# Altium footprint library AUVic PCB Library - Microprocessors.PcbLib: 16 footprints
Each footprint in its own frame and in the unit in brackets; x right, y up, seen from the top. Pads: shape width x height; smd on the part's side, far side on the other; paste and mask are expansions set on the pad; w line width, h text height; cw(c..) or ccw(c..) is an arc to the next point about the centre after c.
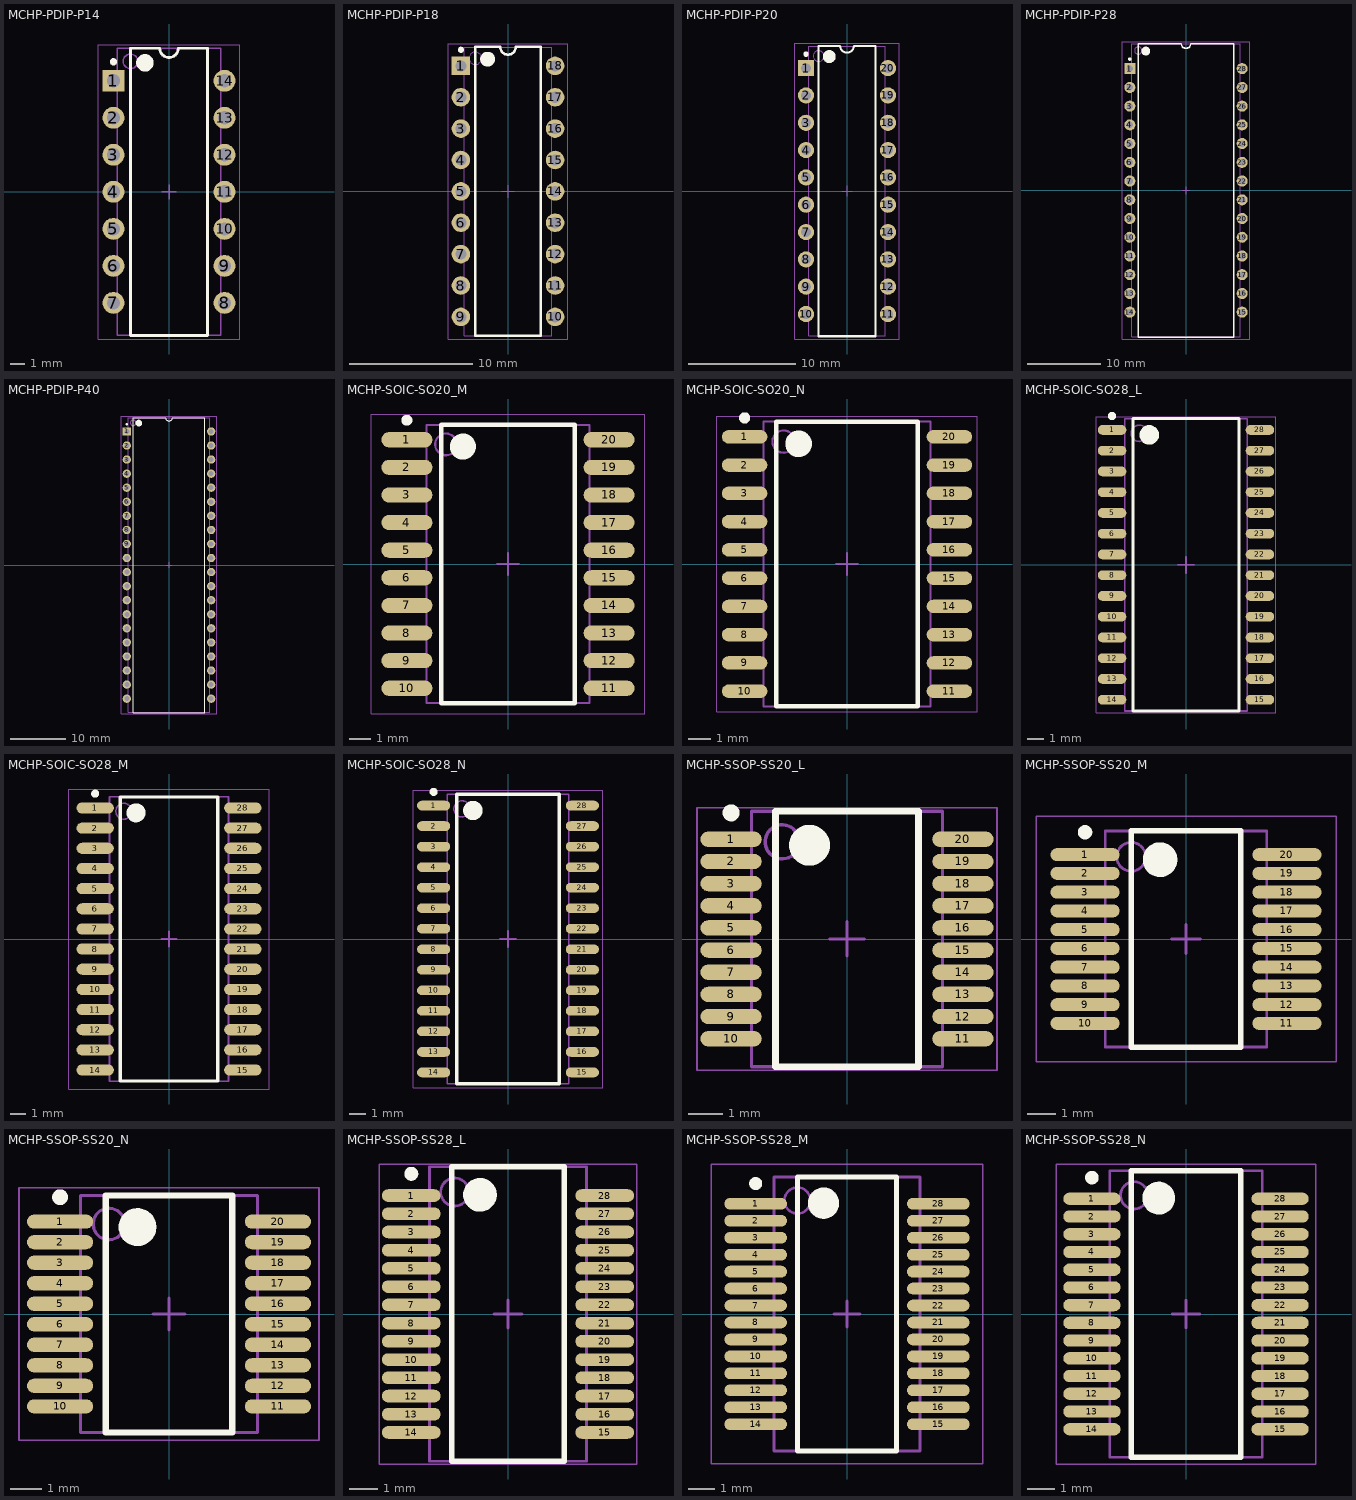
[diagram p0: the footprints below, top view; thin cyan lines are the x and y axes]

## MCHP-PDIP-P14 [mm] "DIP, 14-Leads, Body 19.177x6.604mm, Pitch 2.54mm"
height 5.34
pads (14):
  rect 1.5x1.5 hole 0.9: 1(-3.81,7.62)
  round 1.5 hole 0.9: 2(-3.81,5.08) 3(-3.81,2.54) 4(-3.81,0) 5(-3.81,-2.54) 6(-3.81,-5.08) 7(-3.81,-7.62) 8(3.81,-7.62) 9(3.81,-5.08) 10(3.81,-2.54) 11(3.81,0) 12(3.81,2.54) 13(3.81,5.08) 14(3.81,7.62)
Top Overlay:
  circle w0.25: c-3.81,8.92 r0.125
  circle w0.6: c-1.65,8.85 r0.3
  lines w0.2: -2.65,-9.85 -2.65,9.85 -0.635,9.85 ccw(c0,9.85) 0.635,9.85 2.65,9.85 2.65,-9.85 -2.65,-9.85
Mechanical 13:
  circle w0.1: c-2.65,8.95 r0.5
  lines w0.1: -3.55,-9.85 -3.55,9.85 3.55,9.85 3.55,-9.85 -3.55,-9.85
Mechanical 15:
  lines w0.05: -4.85,-10.1 -4.85,10.1 4.85,10.1 4.85,-10.1 -4.85,-10.1
  lines w0.1: -0.5,0 0.5,0 ; 0,-0.5 0,0.5
3D body: height 2.73, standoff 0, extent -3.945,7.12 -3.675,8.12
3D body: height 3, standoff 2.72, extent -3.945,7.12 -3.55,8.12
3D body: height 0, standoff -1.6, extent -3.945,7.26 -3.675,7.98
3D body: height 2.73, standoff 0, extent -3.945,4.58 -3.675,5.58
3D body: height 3, standoff 2.72, extent -3.945,4.58 -3.55,5.58
3D body: height 0, standoff -1.6, extent -3.945,4.72 -3.675,5.44
3D body: height 2.73, standoff 0, extent -3.945,2.04 -3.675,3.04
3D body: height 3, standoff 2.72, extent -3.945,2.04 -3.55,3.04
3D body: height 0, standoff -1.6, extent -3.945,2.18 -3.675,2.9
3D body: height 2.73, standoff 0, extent -3.945,-0.5 -3.675,0.5
3D body: height 3, standoff 2.72, extent -3.945,-0.5 -3.55,0.5
3D body: height 0, standoff -1.6, extent -3.945,-0.36 -3.675,0.36
3D body: height 2.73, standoff 0, extent -3.945,-3.04 -3.675,-2.04
3D body: height 3, standoff 2.72, extent -3.945,-3.04 -3.55,-2.04
3D body: height 0, standoff -1.6, extent -3.945,-2.9 -3.675,-2.18
3D body: height 2.73, standoff 0, extent -3.945,-5.58 -3.675,-4.58
3D body: height 3, standoff 2.72, extent -3.945,-5.58 -3.55,-4.58
3D body: height 0, standoff -1.6, extent -3.945,-5.44 -3.675,-4.72
3D body: height 2.73, standoff 0, extent -3.945,-8.12 -3.675,-7.12
3D body: height 3, standoff 2.72, extent -3.945,-8.12 -3.55,-7.12
3D body: height 0, standoff -1.6, extent -3.945,-7.98 -3.675,-7.26
3D body: height 2.73, standoff 0, extent 3.675,-8.12 3.945,-7.12
3D body: height 3, standoff 2.72, extent 3.55,-8.12 3.945,-7.12
3D body: height 0, standoff -1.6, extent 3.675,-7.98 3.945,-7.26
3D body: height 2.73, standoff 0, extent 3.675,-5.58 3.945,-4.58
3D body: height 3, standoff 2.72, extent 3.55,-5.58 3.945,-4.58
3D body: height 0, standoff -1.6, extent 3.675,-5.44 3.945,-4.72
3D body: height 2.73, standoff 0, extent 3.675,-3.04 3.945,-2.04
3D body: height 3, standoff 2.72, extent 3.55,-3.04 3.945,-2.04
3D body: height 0, standoff -1.6, extent 3.675,-2.9 3.945,-2.18
3D body: height 2.73, standoff 0, extent 3.675,-0.5 3.945,0.5
3D body: height 3, standoff 2.72, extent 3.55,-0.5 3.945,0.5
3D body: height 0, standoff -1.6, extent 3.675,-0.36 3.945,0.36
3D body: height 2.73, standoff 0, extent 3.675,2.04 3.945,3.04
3D body: height 3, standoff 2.72, extent 3.55,2.04 3.945,3.04
3D body: height 0, standoff -1.6, extent 3.675,2.18 3.945,2.9
3D body: height 2.73, standoff 0, extent 3.675,4.58 3.945,5.58
3D body: height 3, standoff 2.72, extent 3.55,4.58 3.945,5.58
3D body: height 0, standoff -1.6, extent 3.675,4.72 3.945,5.44
3D body: height 2.73, standoff 0, extent 3.675,7.12 3.945,8.12
3D body: height 3, standoff 2.72, extent 3.55,7.12 3.945,8.12
3D body: height 0, standoff -1.6, extent 3.675,7.26 3.945,7.98
3D body: height 5.34, standoff 0.38, extent -3.55,-9.85 3.55,9.85

## MCHP-PDIP-P18 [mm] "DIP, 18-Leads, Body 22.83x6.604mm, Pitch 2.54mm"
height 5.33
pads (18):
  rect 1.5x1.5 hole 0.9: 1(-3.81,10.16)
  round 1.5 hole 0.9: 2(-3.81,7.62) 3(-3.81,5.08) 4(-3.81,2.54) 5(-3.81,0) 6(-3.81,-2.54) 7(-3.81,-5.08) 8(-3.81,-7.62) 9(-3.81,-10.16) 10(3.81,-10.16) 11(3.81,-7.62) 12(3.81,-5.08) 13(3.81,-2.54) 14(3.81,0) 15(3.81,2.54) 16(3.81,5.08) 17(3.81,7.62) 18(3.81,10.16)
Top Overlay:
  circle w0.25: c-3.81,11.46 r0.125
  circle w0.6: c-1.65,10.7 r0.3
  lines w0.2: -2.65,-11.7 -2.65,11.7 -0.635,11.7 ccw(c0,11.7) 0.635,11.7 2.65,11.7 2.65,-11.7 -2.65,-11.7
Mechanical 13:
  circle w0.1: c-2.65,10.775 r0.5
  lines w0.1: -3.55,-11.675 -3.55,11.675 3.55,11.675 3.55,-11.675 -3.55,-11.675
Mechanical 15:
  lines w0.05: -4.85,-11.95 -4.85,11.95 4.85,11.95 4.85,-11.95 -4.85,-11.95
  lines w0.1: -0.5,0 0.5,0 ; 0,-0.5 0,0.5
3D body: height 2.72, standoff 0, extent -3.945,9.66 -3.675,10.66
3D body: height 2.99, standoff 2.72, extent -3.945,9.66 -3.55,10.66
3D body: height 0, standoff -1.6, extent -3.945,9.8 -3.675,10.52
3D body: height 2.72, standoff 0, extent -3.945,7.12 -3.675,8.12
3D body: height 2.99, standoff 2.72, extent -3.945,7.12 -3.55,8.12
3D body: height 0, standoff -1.6, extent -3.945,7.26 -3.675,7.98
3D body: height 2.72, standoff 0, extent -3.945,4.58 -3.675,5.58
3D body: height 2.99, standoff 2.72, extent -3.945,4.58 -3.55,5.58
3D body: height 0, standoff -1.6, extent -3.945,4.72 -3.675,5.44
3D body: height 2.72, standoff 0, extent -3.945,2.04 -3.675,3.04
3D body: height 2.99, standoff 2.72, extent -3.945,2.04 -3.55,3.04
3D body: height 0, standoff -1.6, extent -3.945,2.18 -3.675,2.9
3D body: height 2.72, standoff 0, extent -3.945,-0.5 -3.675,0.5
3D body: height 2.99, standoff 2.72, extent -3.945,-0.5 -3.55,0.5
3D body: height 0, standoff -1.6, extent -3.945,-0.36 -3.675,0.36
3D body: height 2.72, standoff 0, extent -3.945,-3.04 -3.675,-2.04
3D body: height 2.99, standoff 2.72, extent -3.945,-3.04 -3.55,-2.04
3D body: height 0, standoff -1.6, extent -3.945,-2.9 -3.675,-2.18
3D body: height 2.72, standoff 0, extent -3.945,-5.58 -3.675,-4.58
3D body: height 2.99, standoff 2.72, extent -3.945,-5.58 -3.55,-4.58
3D body: height 0, standoff -1.6, extent -3.945,-5.44 -3.675,-4.72
3D body: height 2.72, standoff 0, extent -3.945,-8.12 -3.675,-7.12
3D body: height 2.99, standoff 2.72, extent -3.945,-8.12 -3.55,-7.12
3D body: height 0, standoff -1.6, extent -3.945,-7.98 -3.675,-7.26
3D body: height 2.72, standoff 0, extent -3.945,-10.66 -3.675,-9.66
3D body: height 2.99, standoff 2.72, extent -3.945,-10.66 -3.55,-9.66
3D body: height 0, standoff -1.6, extent -3.945,-10.52 -3.675,-9.8
3D body: height 2.72, standoff 0, extent 3.675,-10.66 3.945,-9.66
3D body: height 2.99, standoff 2.72, extent 3.55,-10.66 3.945,-9.66
3D body: height 0, standoff -1.6, extent 3.675,-10.52 3.945,-9.8
3D body: height 2.72, standoff 0, extent 3.675,-8.12 3.945,-7.12
3D body: height 2.99, standoff 2.72, extent 3.55,-8.12 3.945,-7.12
3D body: height 0, standoff -1.6, extent 3.675,-7.98 3.945,-7.26
3D body: height 2.72, standoff 0, extent 3.675,-5.58 3.945,-4.58
3D body: height 2.99, standoff 2.72, extent 3.55,-5.58 3.945,-4.58
3D body: height 0, standoff -1.6, extent 3.675,-5.44 3.945,-4.72
3D body: height 2.72, standoff 0, extent 3.675,-3.04 3.945,-2.04
3D body: height 2.99, standoff 2.72, extent 3.55,-3.04 3.945,-2.04
3D body: height 0, standoff -1.6, extent 3.675,-2.9 3.945,-2.18
3D body: height 2.72, standoff 0, extent 3.675,-0.5 3.945,0.5
3D body: height 2.99, standoff 2.72, extent 3.55,-0.5 3.945,0.5
3D body: height 0, standoff -1.6, extent 3.675,-0.36 3.945,0.36
3D body: height 2.72, standoff 0, extent 3.675,2.04 3.945,3.04
3D body: height 2.99, standoff 2.72, extent 3.55,2.04 3.945,3.04
3D body: height 0, standoff -1.6, extent 3.675,2.18 3.945,2.9
3D body: height 2.72, standoff 0, extent 3.675,4.58 3.945,5.58
3D body: height 2.99, standoff 2.72, extent 3.55,4.58 3.945,5.58
3D body: height 0, standoff -1.6, extent 3.675,4.72 3.945,5.44
3D body: height 2.72, standoff 0, extent 3.675,7.12 3.945,8.12
3D body: height 2.99, standoff 2.72, extent 3.55,7.12 3.945,8.12
3D body: height 0, standoff -1.6, extent 3.675,7.26 3.945,7.98
3D body: height 2.72, standoff 0, extent 3.675,9.66 3.945,10.66
3D body: height 2.99, standoff 2.72, extent 3.55,9.66 3.945,10.66
3D body: height 0, standoff -1.6, extent 3.675,9.8 3.945,10.52
3D body: height 5.33, standoff 0.38, extent -3.55,-11.675 3.55,11.675

## MCHP-PDIP-P20 [mm] "DIP, 20-Leads, Body 25.91x6.6mm, Pitch 2.54mm"
height 5.34
pads (20):
  rect 1.5x1.5 hole 0.9: 1(-3.81,11.43)
  round 1.5 hole 0.9: 2(-3.81,8.89) 3(-3.81,6.35) 4(-3.81,3.81) 5(-3.81,1.27) 6(-3.81,-1.27) 7(-3.81,-3.81) 8(-3.81,-6.35) 9(-3.81,-8.89) 10(-3.81,-11.43) 11(3.81,-11.43) 12(3.81,-8.89) 13(3.81,-6.35) 14(3.81,-3.81) 15(3.81,-1.27) 16(3.81,1.27) 17(3.81,3.81) 18(3.81,6.35) 19(3.81,8.89) 20(3.81,11.43)
Top Overlay:
  circle w0.25: c-3.81,12.73 r0.125
  circle w0.6: c-1.65,12.5 r0.3
  lines w0.2: -2.65,-13.5 -2.65,13.5 -0.635,13.5 ccw(c0,13.5) 0.635,13.5 2.65,13.5 2.65,-13.5 -2.65,-13.5
Mechanical 13:
  circle w0.1: c-2.65,12.55 r0.5
  lines w0.1: -3.55,-13.45 -3.55,13.45 3.55,13.45 3.55,-13.45 -3.55,-13.45
Mechanical 15:
  lines w0.05: -4.85,-13.75 -4.85,13.75 4.85,13.75 4.85,-13.75 -4.85,-13.75
  lines w0.1: -0.5,0 0.5,0 ; 0,-0.5 0,0.5
3D body: height 2.72, standoff 0, extent -3.945,10.93 -3.675,11.93
3D body: height 2.99, standoff 2.72, extent -3.945,10.93 -3.55,11.93
3D body: height 0, standoff -1.6, extent -3.945,11.07 -3.675,11.79
3D body: height 2.72, standoff 0, extent -3.945,8.39 -3.675,9.39
3D body: height 2.99, standoff 2.72, extent -3.945,8.39 -3.55,9.39
3D body: height 0, standoff -1.6, extent -3.945,8.53 -3.675,9.25
3D body: height 2.72, standoff 0, extent -3.945,5.85 -3.675,6.85
3D body: height 2.99, standoff 2.72, extent -3.945,5.85 -3.55,6.85
3D body: height 0, standoff -1.6, extent -3.945,5.99 -3.675,6.71
3D body: height 2.72, standoff 0, extent -3.945,3.31 -3.675,4.31
3D body: height 2.99, standoff 2.72, extent -3.945,3.31 -3.55,4.31
3D body: height 0, standoff -1.6, extent -3.945,3.45 -3.675,4.17
3D body: height 2.72, standoff 0, extent -3.945,0.77 -3.675,1.77
3D body: height 2.99, standoff 2.72, extent -3.945,0.77 -3.55,1.77
3D body: height 0, standoff -1.6, extent -3.945,0.91 -3.675,1.63
3D body: height 2.72, standoff 0, extent -3.945,-1.77 -3.675,-0.77
3D body: height 2.99, standoff 2.72, extent -3.945,-1.77 -3.55,-0.77
3D body: height 0, standoff -1.6, extent -3.945,-1.63 -3.675,-0.91
3D body: height 2.72, standoff 0, extent -3.945,-4.31 -3.675,-3.31
3D body: height 2.99, standoff 2.72, extent -3.945,-4.31 -3.55,-3.31
3D body: height 0, standoff -1.6, extent -3.945,-4.17 -3.675,-3.45
3D body: height 2.72, standoff 0, extent -3.945,-6.85 -3.675,-5.85
3D body: height 2.99, standoff 2.72, extent -3.945,-6.85 -3.55,-5.85
3D body: height 0, standoff -1.6, extent -3.945,-6.71 -3.675,-5.99
3D body: height 2.72, standoff 0, extent -3.945,-9.39 -3.675,-8.39
3D body: height 2.99, standoff 2.72, extent -3.945,-9.39 -3.55,-8.39
3D body: height 0, standoff -1.6, extent -3.945,-9.25 -3.675,-8.53
3D body: height 2.72, standoff 0, extent -3.945,-11.93 -3.675,-10.93
3D body: height 2.99, standoff 2.72, extent -3.945,-11.93 -3.55,-10.93
3D body: height 0, standoff -1.6, extent -3.945,-11.79 -3.675,-11.07
3D body: height 2.72, standoff 0, extent 3.675,-11.93 3.945,-10.93
3D body: height 2.99, standoff 2.72, extent 3.55,-11.93 3.945,-10.93
3D body: height 0, standoff -1.6, extent 3.675,-11.79 3.945,-11.07
3D body: height 2.72, standoff 0, extent 3.675,-9.39 3.945,-8.39
3D body: height 2.99, standoff 2.72, extent 3.55,-9.39 3.945,-8.39
3D body: height 0, standoff -1.6, extent 3.675,-9.25 3.945,-8.53
3D body: height 2.72, standoff 0, extent 3.675,-6.85 3.945,-5.85
3D body: height 2.99, standoff 2.72, extent 3.55,-6.85 3.945,-5.85
3D body: height 0, standoff -1.6, extent 3.675,-6.71 3.945,-5.99
3D body: height 2.72, standoff 0, extent 3.675,-4.31 3.945,-3.31
3D body: height 2.99, standoff 2.72, extent 3.55,-4.31 3.945,-3.31
3D body: height 0, standoff -1.6, extent 3.675,-4.17 3.945,-3.45
3D body: height 2.72, standoff 0, extent 3.675,-1.77 3.945,-0.77
3D body: height 2.99, standoff 2.72, extent 3.55,-1.77 3.945,-0.77
3D body: height 0, standoff -1.6, extent 3.675,-1.63 3.945,-0.91
3D body: height 2.72, standoff 0, extent 3.675,0.77 3.945,1.77
3D body: height 2.99, standoff 2.72, extent 3.55,0.77 3.945,1.77
3D body: height 0, standoff -1.6, extent 3.675,0.91 3.945,1.63
3D body: height 2.72, standoff 0, extent 3.675,3.31 3.945,4.31
3D body: height 2.99, standoff 2.72, extent 3.55,3.31 3.945,4.31
3D body: height 0, standoff -1.6, extent 3.675,3.45 3.945,4.17
3D body: height 2.72, standoff 0, extent 3.675,5.85 3.945,6.85
3D body: height 2.99, standoff 2.72, extent 3.55,5.85 3.945,6.85
3D body: height 0, standoff -1.6, extent 3.675,5.99 3.945,6.71
3D body: height 2.72, standoff 0, extent 3.675,8.39 3.945,9.39
3D body: height 2.99, standoff 2.72, extent 3.55,8.39 3.945,9.39
3D body: height 0, standoff -1.6, extent 3.675,8.53 3.945,9.25
3D body: height 2.72, standoff 0, extent 3.675,10.93 3.945,11.93
3D body: height 2.99, standoff 2.72, extent 3.55,10.93 3.945,11.93
3D body: height 0, standoff -1.6, extent 3.675,11.07 3.945,11.79
3D body: height 5.34, standoff 0.38, extent -3.55,-13.45 3.55,13.45

## MCHP-PDIP-P28 [mm] "DIP, 28-Leads, Body 37.4x13.53mm, Pitch 2.54mm"
height 6.35
pads (28):
  rect 1.5x1.5 hole 0.9: 1(-7.62,16.51)
  round 1.5 hole 0.9: 2(-7.62,13.97) 3(-7.62,11.43) 4(-7.62,8.89) 5(-7.62,6.35) 6(-7.62,3.81) 7(-7.62,1.27) 8(-7.62,-1.27) 9(-7.62,-3.81) 10(-7.62,-6.35) 11(-7.62,-8.89) 12(-7.62,-11.43) 13(-7.62,-13.97) 14(-7.62,-16.51) 15(7.62,-16.51) 16(7.62,-13.97) 17(7.62,-11.43) 18(7.62,-8.89) 19(7.62,-6.35) 20(7.62,-3.81) 21(7.62,-1.27) 22(7.62,1.27) 23(7.62,3.81) 24(7.62,6.35) 25(7.62,8.89) 26(7.62,11.43) 27(7.62,13.97) 28(7.62,16.51)
Top Overlay:
  circle w0.6: c-5.45,18.9 r0.3
  circle w0.25: c-7.62,17.81 r0.125
  lines w0.2: -6.45,-19.9 6.45,-19.9 6.45,19.9 0.635,19.9 cw(c0,19.9) -0.635,19.9 -6.45,19.9 -6.45,-19.9
Mechanical 13:
  circle w0.1: c-6.475,18.975 r0.5
  lines w0.1: -7.375,-19.875 7.375,-19.875 7.375,19.875 -7.375,19.875 -7.375,-19.875
Mechanical 15:
  lines w0.05: -8.65,-20.15 8.65,-20.15 8.65,20.15 -8.65,20.15 -8.65,-20.15
  lines w0.1: -0.5,0 0.5,0 ; 0,-0.5 0,0.5
3D body: height 6.35, standoff 0.38, extent -7.375,-19.875 7.375,19.875
3D body: height 0, standoff -1.6, extent 7.485,16.15 7.755,16.87
3D body: height 3.51, standoff 3.23, extent 7.375,16.01 7.755,17.01
3D body: height 3.24, standoff 0, extent 7.485,16.01 7.755,17.01
3D body: height 0, standoff -1.6, extent 7.485,13.61 7.755,14.33
3D body: height 3.51, standoff 3.23, extent 7.375,13.47 7.755,14.47
3D body: height 3.24, standoff 0, extent 7.485,13.47 7.755,14.47
3D body: height 0, standoff -1.6, extent 7.485,11.07 7.755,11.79
3D body: height 3.51, standoff 3.23, extent 7.375,10.93 7.755,11.93
3D body: height 3.24, standoff 0, extent 7.485,10.93 7.755,11.93
3D body: height 0, standoff -1.6, extent 7.485,8.53 7.755,9.25
3D body: height 3.51, standoff 3.23, extent 7.375,8.39 7.755,9.39
3D body: height 3.24, standoff 0, extent 7.485,8.39 7.755,9.39
3D body: height 0, standoff -1.6, extent 7.485,5.99 7.755,6.71
3D body: height 3.51, standoff 3.23, extent 7.375,5.85 7.755,6.85
3D body: height 3.24, standoff 0, extent 7.485,5.85 7.755,6.85
3D body: height 0, standoff -1.6, extent 7.485,3.45 7.755,4.17
3D body: height 3.51, standoff 3.23, extent 7.375,3.31 7.755,4.31
3D body: height 3.24, standoff 0, extent 7.485,3.31 7.755,4.31
3D body: height 0, standoff -1.6, extent 7.485,0.91 7.755,1.63
3D body: height 3.51, standoff 3.23, extent 7.375,0.77 7.755,1.77
3D body: height 3.24, standoff 0, extent 7.485,0.77 7.755,1.77
3D body: height 0, standoff -1.6, extent 7.485,-1.63 7.755,-0.91
3D body: height 3.51, standoff 3.23, extent 7.375,-1.77 7.755,-0.77
3D body: height 3.24, standoff 0, extent 7.485,-1.77 7.755,-0.77
3D body: height 0, standoff -1.6, extent 7.485,-4.17 7.755,-3.45
3D body: height 3.51, standoff 3.23, extent 7.375,-4.31 7.755,-3.31
3D body: height 3.24, standoff 0, extent 7.485,-4.31 7.755,-3.31
3D body: height 0, standoff -1.6, extent 7.485,-6.71 7.755,-5.99
3D body: height 3.51, standoff 3.23, extent 7.375,-6.85 7.755,-5.85
3D body: height 3.24, standoff 0, extent 7.485,-6.85 7.755,-5.85
3D body: height 0, standoff -1.6, extent 7.485,-9.25 7.755,-8.53
3D body: height 3.51, standoff 3.23, extent 7.375,-9.39 7.755,-8.39
3D body: height 3.24, standoff 0, extent 7.485,-9.39 7.755,-8.39
3D body: height 0, standoff -1.6, extent 7.485,-11.79 7.755,-11.07
3D body: height 3.51, standoff 3.23, extent 7.375,-11.93 7.755,-10.93
3D body: height 3.24, standoff 0, extent 7.485,-11.93 7.755,-10.93
3D body: height 0, standoff -1.6, extent 7.485,-14.33 7.755,-13.61
3D body: height 3.51, standoff 3.23, extent 7.375,-14.47 7.755,-13.47
3D body: height 3.24, standoff 0, extent 7.485,-14.47 7.755,-13.47
3D body: height 0, standoff -1.6, extent 7.485,-16.87 7.755,-16.15
3D body: height 3.51, standoff 3.23, extent 7.375,-17.01 7.755,-16.01
3D body: height 3.24, standoff 0, extent 7.485,-17.01 7.755,-16.01
3D body: height 0, standoff -1.6, extent -7.755,-16.87 -7.485,-16.15
3D body: height 3.51, standoff 3.23, extent -7.755,-17.01 -7.375,-16.01
3D body: height 3.24, standoff 0, extent -7.755,-17.01 -7.485,-16.01
3D body: height 0, standoff -1.6, extent -7.755,-14.33 -7.485,-13.61
3D body: height 3.51, standoff 3.23, extent -7.755,-14.47 -7.375,-13.47
3D body: height 3.24, standoff 0, extent -7.755,-14.47 -7.485,-13.47
3D body: height 0, standoff -1.6, extent -7.755,-11.79 -7.485,-11.07
3D body: height 3.51, standoff 3.23, extent -7.755,-11.93 -7.375,-10.93
3D body: height 3.24, standoff 0, extent -7.755,-11.93 -7.485,-10.93
3D body: height 0, standoff -1.6, extent -7.755,-9.25 -7.485,-8.53
3D body: height 3.51, standoff 3.23, extent -7.755,-9.39 -7.375,-8.39
3D body: height 3.24, standoff 0, extent -7.755,-9.39 -7.485,-8.39
3D body: height 0, standoff -1.6, extent -7.755,-6.71 -7.485,-5.99
3D body: height 3.51, standoff 3.23, extent -7.755,-6.85 -7.375,-5.85
3D body: height 3.24, standoff 0, extent -7.755,-6.85 -7.485,-5.85
3D body: height 0, standoff -1.6, extent -7.755,-4.17 -7.485,-3.45
3D body: height 3.51, standoff 3.23, extent -7.755,-4.31 -7.375,-3.31
3D body: height 3.24, standoff 0, extent -7.755,-4.31 -7.485,-3.31
3D body: height 0, standoff -1.6, extent -7.755,-1.63 -7.485,-0.91
3D body: height 3.51, standoff 3.23, extent -7.755,-1.77 -7.375,-0.77
3D body: height 3.24, standoff 0, extent -7.755,-1.77 -7.485,-0.77
3D body: height 0, standoff -1.6, extent -7.755,0.91 -7.485,1.63
3D body: height 3.51, standoff 3.23, extent -7.755,0.77 -7.375,1.77
3D body: height 3.24, standoff 0, extent -7.755,0.77 -7.485,1.77
3D body: height 0, standoff -1.6, extent -7.755,3.45 -7.485,4.17
3D body: height 3.51, standoff 3.23, extent -7.755,3.31 -7.375,4.31
3D body: height 3.24, standoff 0, extent -7.755,3.31 -7.485,4.31
3D body: height 0, standoff -1.6, extent -7.755,5.99 -7.485,6.71
3D body: height 3.51, standoff 3.23, extent -7.755,5.85 -7.375,6.85
3D body: height 3.24, standoff 0, extent -7.755,5.85 -7.485,6.85
3D body: height 0, standoff -1.6, extent -7.755,8.53 -7.485,9.25
3D body: height 3.51, standoff 3.23, extent -7.755,8.39 -7.375,9.39
3D body: height 3.24, standoff 0, extent -7.755,8.39 -7.485,9.39
3D body: height 0, standoff -1.6, extent -7.755,11.07 -7.485,11.79
3D body: height 3.51, standoff 3.23, extent -7.755,10.93 -7.375,11.93
3D body: height 3.24, standoff 0, extent -7.755,10.93 -7.485,11.93
3D body: height 0, standoff -1.6, extent -7.755,13.61 -7.485,14.33
3D body: height 3.51, standoff 3.23, extent -7.755,13.47 -7.375,14.47
3D body: height 3.24, standoff 0, extent -7.755,13.47 -7.485,14.47
3D body: height 0, standoff -1.6, extent -7.755,16.15 -7.485,16.87
3D body: height 3.51, standoff 3.23, extent -7.755,16.01 -7.375,17.01
3D body: height 3.24, standoff 0, extent -7.755,16.01 -7.485,17.01

## MCHP-PDIP-P40 [mm] "PDIP, 40-Leads, Body 51.75x13.53mm, Pitch 2.54mm"
height 6.35
pads (40):
  rect 1.5x1.5 hole 0.9: 1(-7.62,24.13)
  round 1.5 hole 0.9: 2(-7.62,21.59) 3(-7.62,19.05) 4(-7.62,16.51) 5(-7.62,13.97) 6(-7.62,11.43) 7(-7.62,8.89) 8(-7.62,6.35) 9(-7.62,3.81) 10(-7.62,1.27) 11(-7.62,-1.27) 12(-7.62,-3.81) 13(-7.62,-6.35) 14(-7.62,-8.89) 15(-7.62,-11.43) 16(-7.62,-13.97) 17(-7.62,-16.51) 18(-7.62,-19.05) 19(-7.62,-21.59) 20(-7.62,-24.13) 21(7.62,-24.13) 22(7.62,-21.59) 23(7.62,-19.05) 24(7.62,-16.51) 25(7.62,-13.97) 26(7.62,-11.43) 27(7.62,-8.89) 28(7.62,-6.35) 29(7.62,-3.81) 30(7.62,-1.27) 31(7.62,1.27) 32(7.62,3.81) 33(7.62,6.35) 34(7.62,8.89) 35(7.62,11.43) 36(7.62,13.97) 37(7.62,16.51) 38(7.62,19.05) 39(7.62,21.59) 40(7.62,24.13)
Top Overlay:
  circle w0.6: c-5.45,25.65 r0.3
  circle w0.25: c-7.62,25.43 r0.125
  lines w0.2: -6.45,-26.65 6.45,-26.65 6.45,26.65 0.635,26.65 cw(c0,26.65) -0.635,26.65 -6.45,26.65 -6.45,-26.65
Mechanical 13:
  circle w0.1: c-6.475,25.7 r0.5
  lines w0.1: -7.375,-26.6 7.375,-26.6 7.375,26.6 -7.375,26.6 -7.375,-26.6
Mechanical 15:
  lines w0.05: -8.65,-26.9 8.65,-26.9 8.65,26.9 -8.65,26.9 -8.65,-26.9
  lines w0.1: -0.5,0 0.5,0 ; 0,-0.5 0,0.5
3D body: height 6.35, standoff 0.38, extent -7.375,-26.6 7.375,26.6
3D body: height 0, standoff -1.6, extent 7.485,23.77 7.755,24.49
3D body: height 3.51, standoff 3.23, extent 7.375,23.63 7.755,24.63
3D body: height 3.24, standoff 0, extent 7.485,23.63 7.755,24.63
3D body: height 0, standoff -1.6, extent 7.485,21.23 7.755,21.95
3D body: height 3.51, standoff 3.23, extent 7.375,21.09 7.755,22.09
3D body: height 3.24, standoff 0, extent 7.485,21.09 7.755,22.09
3D body: height 0, standoff -1.6, extent 7.485,18.69 7.755,19.41
3D body: height 3.51, standoff 3.23, extent 7.375,18.55 7.755,19.55
3D body: height 3.24, standoff 0, extent 7.485,18.55 7.755,19.55
3D body: height 0, standoff -1.6, extent 7.485,16.15 7.755,16.87
3D body: height 3.51, standoff 3.23, extent 7.375,16.01 7.755,17.01
3D body: height 3.24, standoff 0, extent 7.485,16.01 7.755,17.01
3D body: height 0, standoff -1.6, extent 7.485,13.61 7.755,14.33
3D body: height 3.51, standoff 3.23, extent 7.375,13.47 7.755,14.47
3D body: height 3.24, standoff 0, extent 7.485,13.47 7.755,14.47
3D body: height 0, standoff -1.6, extent 7.485,11.07 7.755,11.79
3D body: height 3.51, standoff 3.23, extent 7.375,10.93 7.755,11.93
3D body: height 3.24, standoff 0, extent 7.485,10.93 7.755,11.93
3D body: height 0, standoff -1.6, extent 7.485,8.53 7.755,9.25
3D body: height 3.51, standoff 3.23, extent 7.375,8.39 7.755,9.39
3D body: height 3.24, standoff 0, extent 7.485,8.39 7.755,9.39
3D body: height 0, standoff -1.6, extent 7.485,5.99 7.755,6.71
3D body: height 3.51, standoff 3.23, extent 7.375,5.85 7.755,6.85
3D body: height 3.24, standoff 0, extent 7.485,5.85 7.755,6.85
3D body: height 0, standoff -1.6, extent 7.485,3.45 7.755,4.17
3D body: height 3.51, standoff 3.23, extent 7.375,3.31 7.755,4.31
3D body: height 3.24, standoff 0, extent 7.485,3.31 7.755,4.31
3D body: height 0, standoff -1.6, extent 7.485,0.91 7.755,1.63
3D body: height 3.51, standoff 3.23, extent 7.375,0.77 7.755,1.77
3D body: height 3.24, standoff 0, extent 7.485,0.77 7.755,1.77
3D body: height 0, standoff -1.6, extent 7.485,-1.63 7.755,-0.91
3D body: height 3.51, standoff 3.23, extent 7.375,-1.77 7.755,-0.77
3D body: height 3.24, standoff 0, extent 7.485,-1.77 7.755,-0.77
3D body: height 0, standoff -1.6, extent 7.485,-4.17 7.755,-3.45
3D body: height 3.51, standoff 3.23, extent 7.375,-4.31 7.755,-3.31
3D body: height 3.24, standoff 0, extent 7.485,-4.31 7.755,-3.31
3D body: height 0, standoff -1.6, extent 7.485,-6.71 7.755,-5.99
3D body: height 3.51, standoff 3.23, extent 7.375,-6.85 7.755,-5.85
3D body: height 3.24, standoff 0, extent 7.485,-6.85 7.755,-5.85
3D body: height 0, standoff -1.6, extent 7.485,-9.25 7.755,-8.53
3D body: height 3.51, standoff 3.23, extent 7.375,-9.39 7.755,-8.39
3D body: height 3.24, standoff 0, extent 7.485,-9.39 7.755,-8.39
3D body: height 0, standoff -1.6, extent 7.485,-11.79 7.755,-11.07
3D body: height 3.51, standoff 3.23, extent 7.375,-11.93 7.755,-10.93
3D body: height 3.24, standoff 0, extent 7.485,-11.93 7.755,-10.93
3D body: height 0, standoff -1.6, extent 7.485,-14.33 7.755,-13.61
3D body: height 3.51, standoff 3.23, extent 7.375,-14.47 7.755,-13.47
3D body: height 3.24, standoff 0, extent 7.485,-14.47 7.755,-13.47
3D body: height 0, standoff -1.6, extent 7.485,-16.87 7.755,-16.15
3D body: height 3.51, standoff 3.23, extent 7.375,-17.01 7.755,-16.01
3D body: height 3.24, standoff 0, extent 7.485,-17.01 7.755,-16.01
3D body: height 0, standoff -1.6, extent 7.485,-19.41 7.755,-18.69
3D body: height 3.51, standoff 3.23, extent 7.375,-19.55 7.755,-18.55
3D body: height 3.24, standoff 0, extent 7.485,-19.55 7.755,-18.55
3D body: height 0, standoff -1.6, extent 7.485,-21.95 7.755,-21.23
3D body: height 3.51, standoff 3.23, extent 7.375,-22.09 7.755,-21.09
3D body: height 3.24, standoff 0, extent 7.485,-22.09 7.755,-21.09
3D body: height 0, standoff -1.6, extent 7.485,-24.49 7.755,-23.77
3D body: height 3.51, standoff 3.23, extent 7.375,-24.63 7.755,-23.63
3D body: height 3.24, standoff 0, extent 7.485,-24.63 7.755,-23.63
3D body: height 0, standoff -1.6, extent -7.755,-24.49 -7.485,-23.77
3D body: height 3.51, standoff 3.23, extent -7.755,-24.63 -7.375,-23.63
3D body: height 3.24, standoff 0, extent -7.755,-24.63 -7.485,-23.63
3D body: height 0, standoff -1.6, extent -7.755,-21.95 -7.485,-21.23
3D body: height 3.51, standoff 3.23, extent -7.755,-22.09 -7.375,-21.09
3D body: height 3.24, standoff 0, extent -7.755,-22.09 -7.485,-21.09
3D body: height 0, standoff -1.6, extent -7.755,-19.41 -7.485,-18.69
3D body: height 3.51, standoff 3.23, extent -7.755,-19.55 -7.375,-18.55
3D body: height 3.24, standoff 0, extent -7.755,-19.55 -7.485,-18.55
3D body: height 0, standoff -1.6, extent -7.755,-16.87 -7.485,-16.15
3D body: height 3.51, standoff 3.23, extent -7.755,-17.01 -7.375,-16.01
3D body: height 3.24, standoff 0, extent -7.755,-17.01 -7.485,-16.01
3D body: height 0, standoff -1.6, extent -7.755,-14.33 -7.485,-13.61
3D body: height 3.51, standoff 3.23, extent -7.755,-14.47 -7.375,-13.47
3D body: height 3.24, standoff 0, extent -7.755,-14.47 -7.485,-13.47
3D body: height 0, standoff -1.6, extent -7.755,-11.79 -7.485,-11.07
3D body: height 3.51, standoff 3.23, extent -7.755,-11.93 -7.375,-10.93
3D body: height 3.24, standoff 0, extent -7.755,-11.93 -7.485,-10.93
3D body: height 0, standoff -1.6, extent -7.755,-9.25 -7.485,-8.53
3D body: height 3.51, standoff 3.23, extent -7.755,-9.39 -7.375,-8.39
3D body: height 3.24, standoff 0, extent -7.755,-9.39 -7.485,-8.39
3D body: height 0, standoff -1.6, extent -7.755,-6.71 -7.485,-5.99
3D body: height 3.51, standoff 3.23, extent -7.755,-6.85 -7.375,-5.85
3D body: height 3.24, standoff 0, extent -7.755,-6.85 -7.485,-5.85
3D body: height 0, standoff -1.6, extent -7.755,-4.17 -7.485,-3.45
3D body: height 3.51, standoff 3.23, extent -7.755,-4.31 -7.375,-3.31
3D body: height 3.24, standoff 0, extent -7.755,-4.31 -7.485,-3.31
3D body: height 0, standoff -1.6, extent -7.755,-1.63 -7.485,-0.91
3D body: height 3.51, standoff 3.23, extent -7.755,-1.77 -7.375,-0.77
3D body: height 3.24, standoff 0, extent -7.755,-1.77 -7.485,-0.77
3D body: height 0, standoff -1.6, extent -7.755,0.91 -7.485,1.63
3D body: height 3.51, standoff 3.23, extent -7.755,0.77 -7.375,1.77
3D body: height 3.24, standoff 0, extent -7.755,0.77 -7.485,1.77
3D body: height 0, standoff -1.6, extent -7.755,3.45 -7.485,4.17
3D body: height 3.51, standoff 3.23, extent -7.755,3.31 -7.375,4.31
3D body: height 3.24, standoff 0, extent -7.755,3.31 -7.485,4.31
3D body: height 0, standoff -1.6, extent -7.755,5.99 -7.485,6.71
3D body: height 3.51, standoff 3.23, extent -7.755,5.85 -7.375,6.85
3D body: height 3.24, standoff 0, extent -7.755,5.85 -7.485,6.85
3D body: height 0, standoff -1.6, extent -7.755,8.53 -7.485,9.25
3D body: height 3.51, standoff 3.23, extent -7.755,8.39 -7.375,9.39
3D body: height 3.24, standoff 0, extent -7.755,8.39 -7.485,9.39
3D body: height 0, standoff -1.6, extent -7.755,11.07 -7.485,11.79
3D body: height 3.51, standoff 3.23, extent -7.755,10.93 -7.375,11.93
3D body: height 3.24, standoff 0, extent -7.755,10.93 -7.485,11.93
3D body: height 0, standoff -1.6, extent -7.755,13.61 -7.485,14.33
3D body: height 3.51, standoff 3.23, extent -7.755,13.47 -7.375,14.47
3D body: height 3.24, standoff 0, extent -7.755,13.47 -7.485,14.47
3D body: height 0, standoff -1.6, extent -7.755,16.15 -7.485,16.87
3D body: height 3.51, standoff 3.23, extent -7.755,16.01 -7.375,17.01
3D body: height 3.24, standoff 0, extent -7.755,16.01 -7.485,17.01
3D body: height 0, standoff -1.6, extent -7.755,18.69 -7.485,19.41
3D body: height 3.51, standoff 3.23, extent -7.755,18.55 -7.375,19.55
3D body: height 3.24, standoff 0, extent -7.755,18.55 -7.485,19.55
3D body: height 0, standoff -1.6, extent -7.755,21.23 -7.485,21.95
3D body: height 3.51, standoff 3.23, extent -7.755,21.09 -7.375,22.09
3D body: height 3.24, standoff 0, extent -7.755,21.09 -7.485,22.09
3D body: height 0, standoff -1.6, extent -7.755,23.77 -7.485,24.49
3D body: height 3.51, standoff 3.23, extent -7.755,23.63 -7.375,24.63
3D body: height 3.24, standoff 0, extent -7.755,23.63 -7.485,24.63

## MCHP-SOIC-SO20_M [mm] "SOIC, 20-Leads, Body 12.8x7.5mm, Pitch 1.27mm, IPC Low Density"
height 2.65
pads (20):
  oval 2.35x0.7 smd: 1(-4.65,5.715) 2(-4.65,4.445) 3(-4.65,3.175) 4(-4.65,1.905) 5(-4.65,0.635) 6(-4.65,-0.635) 7(-4.65,-1.905) 8(-4.65,-3.175) 9(-4.65,-4.445) 10(-4.65,-5.715) 11(4.65,-5.715) 12(4.65,-4.445) 13(4.65,-3.175) 14(4.65,-1.905) 15(4.65,-0.635) 16(4.65,0.635) 17(4.65,1.905) 18(4.65,3.175) 19(4.65,4.445) 20(4.65,5.715)
Top Overlay:
  circle w0.25: c-4.65,6.615 r0.125
  circle w0.6: c-2.075,5.4 r0.3
  lines w0.2: -3.075,-6.4 -3.075,6.4 3.075,6.4 3.075,-6.4 -3.075,-6.4
Mechanical 13:
  circle w0.1: c-2.85,5.5 r0.5
  lines w0.1: -3.75,-6.4 -3.75,6.4 3.75,6.4 3.75,-6.4 -3.75,-6.4
Mechanical 15:
  lines w0.05: -6.3,-6.9 -6.3,6.9 6.3,6.9 6.3,-6.9 -6.3,-6.9
  lines w0.1: -0.5,0 0.5,0 ; 0,-0.5 0,0.5
3D body: height 2.65, standoff 0.1, extent -3.75,-6.4 3.75,6.4

## MCHP-SOIC-SO20_N [mm] "SOIC, 20-Leads, Body 12.8x7.5mm, Pitch 1.27mm, IPC Medium Density"
height 2.65
pads (20):
  oval 2.05x0.6 smd: 1(-4.6,5.715) 2(-4.6,4.445) 3(-4.6,3.175) 4(-4.6,1.905) 5(-4.6,0.635) 6(-4.6,-0.635) 7(-4.6,-1.905) 8(-4.6,-3.175) 9(-4.6,-4.445) 10(-4.6,-5.715) 11(4.6,-5.715) 12(4.6,-4.445) 13(4.6,-3.175) 14(4.6,-1.905) 15(4.6,-0.635) 16(4.6,0.635) 17(4.6,1.905) 18(4.6,3.175) 19(4.6,4.445) 20(4.6,5.715)
Top Overlay:
  circle w0.6: c-2.175,5.4 r0.3
  circle w0.25: c-4.6,6.565 r0.125
  lines w0.2: -3.175,-6.4 3.175,-6.4 3.175,6.4 -3.175,6.4 -3.175,-6.4
Mechanical 13:
  circle w0.1: c-2.85,5.5 r0.5
  lines w0.1: -3.75,-6.4 3.75,-6.4 3.75,6.4 -3.75,6.4 -3.75,-6.4
Mechanical 15:
  lines w0.05: -5.85,-6.65 5.85,-6.65 5.85,6.65 -5.85,6.65 -5.85,-6.65
  lines w0.1: -0.5,0 0.5,0 ; 0,-0.5 0,0.5
3D body: height 2.65, standoff 0.1, extent -3.75,-6.4 3.75,6.4

## MCHP-SOIC-SO28_L [mm] "SOIC, 28-Leads, Body 17.9x7.5mm, Pitch 1.27mm, IPC High Density"
height 2.65
pads (28):
  oval 1.75x0.6 smd: 1(-4.525,8.255) 2(-4.525,6.985) 3(-4.525,5.715) 4(-4.525,4.445) 5(-4.525,3.175) 6(-4.525,1.905) 7(-4.525,0.635) 8(-4.525,-0.635) 9(-4.525,-1.905) 10(-4.525,-3.175) 11(-4.525,-4.445) 12(-4.525,-5.715) 13(-4.525,-6.985) 14(-4.525,-8.255) 15(4.525,-8.255) 16(4.525,-6.985) 17(4.525,-5.715) 18(4.525,-4.445) 19(4.525,-3.175) 20(4.525,-1.905) 21(4.525,-0.635) 22(4.525,0.635) 23(4.525,1.905) 24(4.525,3.175) 25(4.525,4.445) 26(4.525,5.715) 27(4.525,6.985) 28(4.525,8.255)
Top Overlay:
  circle w0.6: c-2.25,7.95 r0.3
  circle w0.25: c-4.525,9.105 r0.125
  lines w0.2: -3.25,-8.95 3.25,-8.95 3.25,8.95 -3.25,8.95 -3.25,-8.95
Mechanical 13:
  circle w0.1: c-2.85,8.05 r0.5
  lines w0.1: -3.75,-8.95 3.75,-8.95 3.75,8.95 -3.75,8.95 -3.75,-8.95
Mechanical 15:
  lines w0.05: -5.5,-9.05 5.5,-9.05 5.5,9.05 -5.5,9.05 -5.5,-9.05
  lines w0.1: -0.5,0 0.5,0 ; 0,-0.5 0,0.5
3D body: height 2.65, standoff 0.1, extent -3.75,-8.95 3.75,8.95

## MCHP-SOIC-SO28_M [mm] "SOIC, 28-Leads, Body 17.9x7.5mm, Pitch 1.27mm, IPC Low Density"
height 2.65
pads (28):
  oval 2.35x0.7 smd: 1(-4.65,8.255) 2(-4.65,6.985) 3(-4.65,5.715) 4(-4.65,4.445) 5(-4.65,3.175) 6(-4.65,1.905) 7(-4.65,0.635) 8(-4.65,-0.635) 9(-4.65,-1.905) 10(-4.65,-3.175) 11(-4.65,-4.445) 12(-4.65,-5.715) 13(-4.65,-6.985) 14(-4.65,-8.255) 15(4.65,-8.255) 16(4.65,-6.985) 17(4.65,-5.715) 18(4.65,-4.445) 19(4.65,-3.175) 20(4.65,-1.905) 21(4.65,-0.635) 22(4.65,0.635) 23(4.65,1.905) 24(4.65,3.175) 25(4.65,4.445) 26(4.65,5.715) 27(4.65,6.985) 28(4.65,8.255)
Top Overlay:
  circle w0.6: c-2.075,7.95 r0.3
  circle w0.25: c-4.65,9.155 r0.125
  lines w0.2: -3.075,-8.95 3.075,-8.95 3.075,8.95 -3.075,8.95 -3.075,-8.95
Mechanical 13:
  circle w0.1: c-2.85,8.05 r0.5
  lines w0.1: -3.75,-8.95 3.75,-8.95 3.75,8.95 -3.75,8.95 -3.75,-8.95
Mechanical 15:
  lines w0.05: -6.3,-9.45 6.3,-9.45 6.3,9.45 -6.3,9.45 -6.3,-9.45
  lines w0.1: -0.5,0 0.5,0 ; 0,-0.5 0,0.5
3D body: height 2.65, standoff 0.1, extent -3.75,-8.95 3.75,8.95

## MCHP-SOIC-SO28_N [mm] "SOIC, 28-Leads, Body 17.9x7.5mm, Pitch 1.27mm, IPC Medium Density"
height 2.65
pads (28):
  oval 2.05x0.6 smd: 1(-4.6,8.255) 2(-4.6,6.985) 3(-4.6,5.715) 4(-4.6,4.445) 5(-4.6,3.175) 6(-4.6,1.905) 7(-4.6,0.635) 8(-4.6,-0.635) 9(-4.6,-1.905) 10(-4.6,-3.175) 11(-4.6,-4.445) 12(-4.6,-5.715) 13(-4.6,-6.985) 14(-4.6,-8.255) 15(4.6,-8.255) 16(4.6,-6.985) 17(4.6,-5.715) 18(4.6,-4.445) 19(4.6,-3.175) 20(4.6,-1.905) 21(4.6,-0.635) 22(4.6,0.635) 23(4.6,1.905) 24(4.6,3.175) 25(4.6,4.445) 26(4.6,5.715) 27(4.6,6.985) 28(4.6,8.255)
Top Overlay:
  circle w0.6: c-2.175,7.95 r0.3
  circle w0.25: c-4.6,9.105 r0.125
  lines w0.2: -3.175,-8.95 3.175,-8.95 3.175,8.95 -3.175,8.95 -3.175,-8.95
Mechanical 13:
  circle w0.1: c-2.85,8.05 r0.5
  lines w0.1: -3.75,-8.95 3.75,-8.95 3.75,8.95 -3.75,8.95 -3.75,-8.95
Mechanical 15:
  lines w0.05: -5.85,-9.2 5.85,-9.2 5.85,9.2 -5.85,9.2 -5.85,-9.2
  lines w0.1: -0.5,0 0.5,0 ; 0,-0.5 0,0.5
3D body: height 2.65, standoff 0.1, extent -3.75,-8.95 3.75,8.95

## MCHP-SSOP-SS20_L [mm] "SOP, 20-Leads, Body 7.2x5.3mm, Pitch 0.65mm, IPC High Density"
height 2
pads (20):
  oval 1.8x0.45 smd: 1(-3.4,2.925) 2(-3.4,2.275) 3(-3.4,1.625) 4(-3.4,0.975) 5(-3.4,0.325) 6(-3.4,-0.325) 7(-3.4,-0.975) 8(-3.4,-1.625) 9(-3.4,-2.275) 10(-3.4,-2.925) 11(3.4,-2.925) 12(3.4,-2.275) 13(3.4,-1.625) 14(3.4,-0.975) 15(3.4,-0.325) 16(3.4,0.325) 17(3.4,0.975) 18(3.4,1.625) 19(3.4,2.275) 20(3.4,2.925)
Top Overlay:
  circle w0.25: c-3.4,3.7 r0.125
  circle w0.6: c-1.1,2.75 r0.3
  lines w0.2: -2.1,-3.75 -2.1,3.75 2.1,3.75 2.1,-3.75 -2.1,-3.75
Mechanical 13:
  circle w0.1: c-1.9,2.85 r0.5
  lines w0.1: -2.8,-3.75 -2.8,3.75 2.8,3.75 2.8,-3.75 -2.8,-3.75
Mechanical 15:
  lines w0.05: -4.4,-3.85 -4.4,3.85 4.4,3.85 4.4,-3.85 -4.4,-3.85
  lines w0.1: -0.5,0 0.5,0 ; 0,-0.5 0,0.5
3D body: height 2, standoff 0.05, extent -2.8,-3.75 2.8,3.75

## MCHP-SSOP-SS20_M [mm] "SOP, 20-Leads, Body 7.2x5.3mm, Pitch 0.65mm, IPC Low Density"
height 2
pads (20):
  oval 2.4x0.45 smd: 1(-3.5,2.925) 2(-3.5,2.275) 3(-3.5,1.625) 4(-3.5,0.975) 5(-3.5,0.325) 6(-3.5,-0.325) 7(-3.5,-0.975) 8(-3.5,-1.625) 9(-3.5,-2.275) 10(-3.5,-2.925) 11(3.5,-2.925) 12(3.5,-2.275) 13(3.5,-1.625) 14(3.5,-0.975) 15(3.5,-0.325) 16(3.5,0.325) 17(3.5,0.975) 18(3.5,1.625) 19(3.5,2.275) 20(3.5,2.925)
Top Overlay:
  circle w0.25: c-3.5,3.7 r0.125
  circle w0.6: c-0.9,2.75 r0.3
  lines w0.2: -1.9,-3.75 -1.9,3.75 1.9,3.75 1.9,-3.75 -1.9,-3.75
Mechanical 13:
  circle w0.1: c-1.9,2.85 r0.5
  lines w0.1: -2.8,-3.75 -2.8,3.75 2.8,3.75 2.8,-3.75 -2.8,-3.75
Mechanical 15:
  lines w0.05: -5.2,-4.25 -5.2,4.25 5.2,4.25 5.2,-4.25 -5.2,-4.25
  lines w0.1: -0.5,0 0.5,0 ; 0,-0.5 0,0.5
3D body: height 2, standoff 0.05, extent -2.8,-3.75 2.8,3.75

## MCHP-SSOP-SS20_N [mm] "SOP, 20-Leads, Body 7.2x5.3mm, Pitch 0.65mm, IPC Medium Density"
height 2
pads (20):
  oval 2.1x0.45 smd: 1(-3.45,2.925) 2(-3.45,2.275) 3(-3.45,1.625) 4(-3.45,0.975) 5(-3.45,0.325) 6(-3.45,-0.325) 7(-3.45,-0.975) 8(-3.45,-1.625) 9(-3.45,-2.275) 10(-3.45,-2.925) 11(3.45,-2.925) 12(3.45,-2.275) 13(3.45,-1.625) 14(3.45,-0.975) 15(3.45,-0.325) 16(3.45,0.325) 17(3.45,0.975) 18(3.45,1.625) 19(3.45,2.275) 20(3.45,2.925)
Top Overlay:
  circle w0.25: c-3.45,3.7 r0.125
  circle w0.6: c-1,2.75 r0.3
  lines w0.2: -2,-3.75 -2,3.75 2,3.75 2,-3.75 -2,-3.75
Mechanical 13:
  circle w0.1: c-1.9,2.85 r0.5
  lines w0.1: -2.8,-3.75 -2.8,3.75 2.8,3.75 2.8,-3.75 -2.8,-3.75
Mechanical 15:
  lines w0.05: -4.75,-4 -4.75,4 4.75,4 4.75,-4 -4.75,-4
  lines w0.1: -0.5,0 0.5,0 ; 0,-0.5 0,0.5
3D body: height 2, standoff 0.05, extent -2.8,-3.75 2.8,3.75

## MCHP-SSOP-SS28_L [mm] "SOP, 28-Leads, Body 10.2x5.3mm, Pitch 0.65mm, IPC High Density"
height 2
pads (28):
  oval 2.1x0.45 smd: 1(-3.45,4.225) 2(-3.45,3.575) 3(-3.45,2.925) 4(-3.45,2.275) 5(-3.45,1.625) 6(-3.45,0.975) 7(-3.45,0.325) 8(-3.45,-0.325) 9(-3.45,-0.975) 10(-3.45,-1.625) 11(-3.45,-2.275) 12(-3.45,-2.925) 13(-3.45,-3.575) 14(-3.45,-4.225) 15(3.45,-4.225) 16(3.45,-3.575) 17(3.45,-2.925) 18(3.45,-2.275) 19(3.45,-1.625) 20(3.45,-0.975) 21(3.45,-0.325) 22(3.45,0.325) 23(3.45,0.975) 24(3.45,1.625) 25(3.45,2.275) 26(3.45,2.925) 27(3.45,3.575) 28(3.45,4.225)
Top Overlay:
  circle w0.6: c-1,4.25 r0.3
  circle w0.25: c-3.45,5 r0.125
  lines w0.2: -2,-5.25 2,-5.25 2,5.25 -2,5.25 -2,-5.25
Mechanical 13:
  circle w0.1: c-1.9,4.35 r0.5
  lines w0.1: -2.8,-5.25 2.8,-5.25 2.8,5.25 -2.8,5.25 -2.8,-5.25
Mechanical 15:
  lines w0.05: -4.6,-5.35 4.6,-5.35 4.6,5.35 -4.6,5.35 -4.6,-5.35
  lines w0.1: -0.5,0 0.5,0 ; 0,-0.5 0,0.5
3D body: height 2, standoff 0.05, extent -2.8,-5.25 2.8,5.25

## MCHP-SSOP-SS28_M [mm] "SOP, 28-Leads, Body 10.2x5.3mm, Pitch 0.65mm, IPC Low Density"
height 2
pads (28):
  oval 2.4x0.45 smd: 1(-3.5,4.225) 2(-3.5,3.575) 3(-3.5,2.925) 4(-3.5,2.275) 5(-3.5,1.625) 6(-3.5,0.975) 7(-3.5,0.325) 8(-3.5,-0.325) 9(-3.5,-0.975) 10(-3.5,-1.625) 11(-3.5,-2.275) 12(-3.5,-2.925) 13(-3.5,-3.575) 14(-3.5,-4.225) 15(3.5,-4.225) 16(3.5,-3.575) 17(3.5,-2.925) 18(3.5,-2.275) 19(3.5,-1.625) 20(3.5,-0.975) 21(3.5,-0.325) 22(3.5,0.325) 23(3.5,0.975) 24(3.5,1.625) 25(3.5,2.275) 26(3.5,2.925) 27(3.5,3.575) 28(3.5,4.225)
Top Overlay:
  circle w0.6: c-0.9,4.25 r0.3
  circle w0.25: c-3.5,5 r0.125
  lines w0.2: -1.9,-5.25 1.9,-5.25 1.9,5.25 -1.9,5.25 -1.9,-5.25
Mechanical 13:
  circle w0.1: c-1.9,4.35 r0.5
  lines w0.1: -2.8,-5.25 2.8,-5.25 2.8,5.25 -2.8,5.25 -2.8,-5.25
Mechanical 15:
  lines w0.05: -5.2,-5.75 5.2,-5.75 5.2,5.75 -5.2,5.75 -5.2,-5.75
  lines w0.1: -0.5,0 0.5,0 ; 0,-0.5 0,0.5
3D body: height 2, standoff 0.05, extent -2.8,-5.25 2.8,5.25

## MCHP-SSOP-SS28_N [mm] "SOP, 28-Leads, Body 10.2x5.3mm, Pitch 0.65mm, IPC Medium Density"
height 2
pads (28):
  oval 2.1x0.45 smd: 1(-3.45,4.225) 2(-3.45,3.575) 3(-3.45,2.925) 4(-3.45,2.275) 5(-3.45,1.625) 6(-3.45,0.975) 7(-3.45,0.325) 8(-3.45,-0.325) 9(-3.45,-0.975) 10(-3.45,-1.625) 11(-3.45,-2.275) 12(-3.45,-2.925) 13(-3.45,-3.575) 14(-3.45,-4.225) 15(3.45,-4.225) 16(3.45,-3.575) 17(3.45,-2.925) 18(3.45,-2.275) 19(3.45,-1.625) 20(3.45,-0.975) 21(3.45,-0.325) 22(3.45,0.325) 23(3.45,0.975) 24(3.45,1.625) 25(3.45,2.275) 26(3.45,2.925) 27(3.45,3.575) 28(3.45,4.225)
Top Overlay:
  circle w0.6: c-1,4.25 r0.3
  circle w0.25: c-3.45,5 r0.125
  lines w0.2: -2,-5.25 2,-5.25 2,5.25 -2,5.25 -2,-5.25
Mechanical 13:
  circle w0.1: c-1.9,4.35 r0.5
  lines w0.1: -2.8,-5.25 2.8,-5.25 2.8,5.25 -2.8,5.25 -2.8,-5.25
Mechanical 15:
  lines w0.05: -4.75,-5.5 4.75,-5.5 4.75,5.5 -4.75,5.5 -4.75,-5.5
  lines w0.1: -0.5,0 0.5,0 ; 0,-0.5 0,0.5
3D body: height 2, standoff 0.05, extent -2.8,-5.25 2.8,5.25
